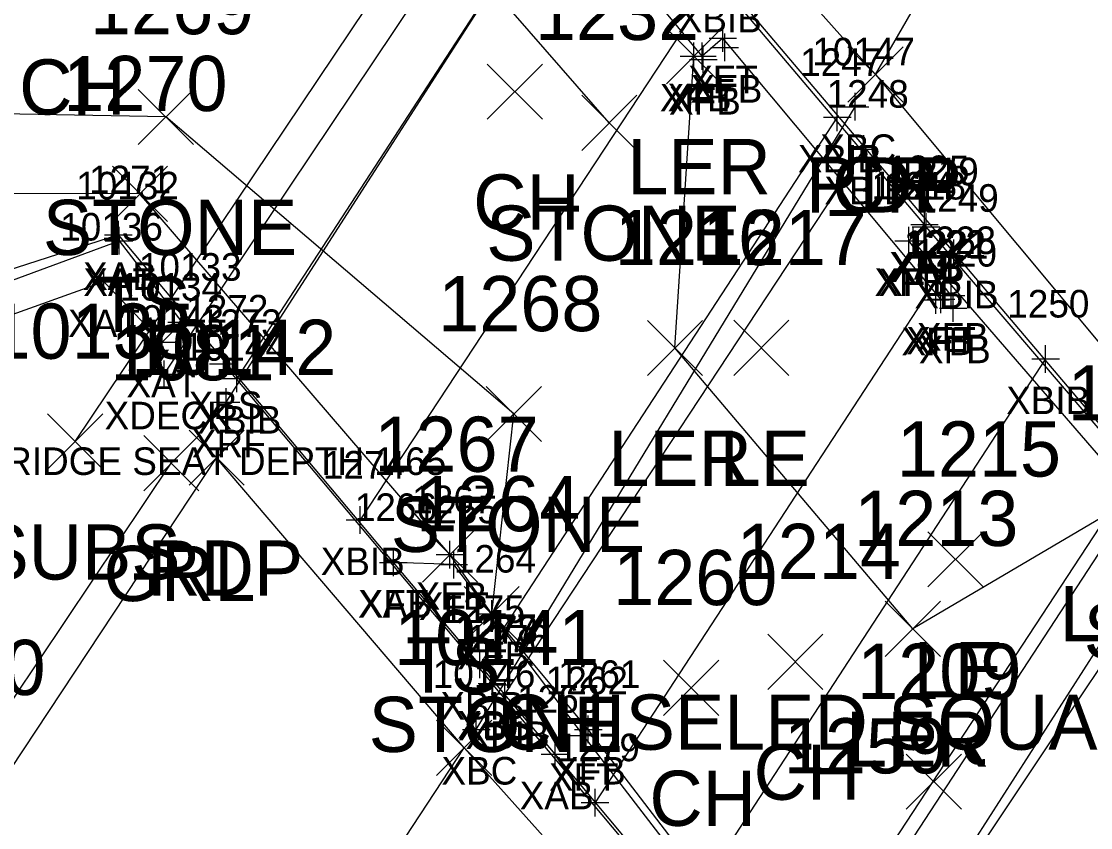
# Model space of a CAD drawing. Extents: x 1651685 to 1653558, y 889533 to 891085.
# Drawn here: x 1652681.1 to 1652719.83, y 890246.97 to 890276.18 of the extents above; entities that cross this region are included whole.
import ezdxf

# ---------------------------------------------------------------- set-up
doc = ezdxf.new("R2010")
doc.units = 0
for name, color, linetype in [('B_A', 7, 'Continuous'), ('B_C', 7, 'Continuous'), ('B_I', 7, 'Continuous'), ('B_TIC', 7, 'Continuous'), ('BB', 7, 'Continuous'), ('BELB', 7, 'Continuous'), ('BFT', 7, 'Continuous'), ('BR', 7, 'Continuous'), ('BSE', 7, 'Continuous'), ('BSUBM', 7, 'Continuous'), ('C_C', 7, 'Continuous'), ('L_A', 7, 'Continuous'), ('L_I', 7, 'Continuous'), ('L_TIC', 7, 'Continuous'), ('LARO', 7, 'Continuous'), ('LASF', 7, 'Continuous'), ('LELB', 7, 'Continuous'), ('P_A', 7, 'Continuous'), ('P_I', 7, 'Continuous'), ('P_TIC', 7, 'Continuous'), ('PET', 7, 'Continuous'), ('PRC', 7, 'Continuous'), ('R_A', 7, 'Continuous'), ('R_I', 7, 'Continuous'), ('R_TIC', 7, 'Continuous'), ('RGR', 7, 'Continuous'), ('U_A', 7, 'Continuous'), ('U_I', 7, 'Continuous'), ('U_TIC', 7, 'Continuous'), ('USA', 7, 'Continuous')]:
    doc.layers.add(name, color=color, linetype=linetype)

msp = doc.modelspace()

# ---------------------------------------------------------------- linework, layer by layer
at = {"layer": 'B_TIC'}
for p, q in [((1652706.515, 890275.575), (1652706.59, 890275.575)), ((1652706.585, 890275.238), (1652706.66, 890275.238)), ((1652705.47, 890274.919), (1652705.545, 890274.919)), ((1652705.769, 890274.921), (1652705.844, 890274.921)), ((1652705.806, 890274.805), (1652705.881, 890274.805)), ((1652711.308, 890273.088), (1652711.383, 890273.088)), ((1652710.662, 890272.707), (1652710.737, 890272.707)), ((1652711.622, 890271.554), (1652711.697, 890271.554)), ((1652713.821, 890268.822), (1652713.896, 890268.822)), ((1652713.821, 890268.822), (1652713.896, 890268.822)), ((1652713.877, 890268.743), (1652713.953, 890268.743)), ((1652713.877, 890268.743), (1652713.953, 890268.743)), ((1652684.618, 890268.453), (1652684.694, 890268.453)), ((1652684.644, 890268.232), (1652684.719, 890268.232)), ((1652713.249, 890268.232), (1652713.324, 890268.232)), ((1652713.408, 890268.228), (1652713.483, 890268.228)), ((1652714.885, 890267.783), (1652714.96, 890267.783)), ((1652684.09, 890266.74), (1652684.166, 890266.74)), ((1652714.785, 890266.251), (1652714.861, 890266.251)), ((1652714.228, 890266.087), (1652714.303, 890266.087)), ((1652714.414, 890266.114), (1652714.49, 890266.114)), ((1652714.859, 890265.796), (1652714.934, 890265.796)), ((1652686.913, 890265.285), (1652686.988, 890265.285)), ((1652686.206, 890264.564), (1652686.282, 890264.564)), ((1652718.208, 890263.952), (1652718.283, 890263.952)), ((1652688.422, 890263.77), (1652688.498, 890263.77)), ((1652686.275, 890263.4), (1652686.351, 890263.4)), ((1652688.906, 890263.246), (1652688.982, 890263.246)), ((1652688.522, 890262.387), (1652688.598, 890262.387)), ((1652693.375, 890258.116), (1652693.451, 890258.116)), ((1652696.63, 890256.861), (1652696.706, 890256.861)), ((1652694.58, 890256.579), (1652694.655, 890256.579)), ((1652694.58, 890256.579), (1652694.655, 890256.579)), ((1652696.767, 890256.497), (1652696.842, 890256.497)), ((1652698.141, 890254.709), (1652698.217, 890254.709)), ((1652697.712, 890252.882), (1652697.788, 890252.882)), ((1652698.154, 890252.192), (1652698.23, 890252.192)), ((1652698.188, 890252.136), (1652698.264, 890252.136)), ((1652698.619, 890251.814), (1652698.695, 890251.814)), ((1652697.585, 890250.528), (1652697.66, 890250.528)), ((1652701.471, 890250.302), (1652701.546, 890250.302)), ((1652701.64, 890250.529), (1652701.715, 890250.529)), ((1652700.436, 890249.63), (1652700.511, 890249.63)), ((1652701.886, 890247.873), (1652701.962, 890247.873))]:
    msp.add_line(p, q, dxfattribs=at)
for points in [[(1652706.512, 890275.075), (1652706.512, 890276.075)], [(1652706.012, 890275.575), (1652707.012, 890275.575)], [(1652706.581, 890274.738), (1652706.581, 890275.738)], [(1652705.466, 890274.419), (1652705.466, 890275.419)], [(1652705.765, 890274.421), (1652705.765, 890275.421)], [(1652705.803, 890274.305), (1652705.803, 890275.305)], [(1652706.081, 890275.238), (1652707.081, 890275.238)], [(1652704.966, 890274.919), (1652705.966, 890274.919)], [(1652705.265, 890274.921), (1652706.265, 890274.921)], [(1652705.303, 890274.805), (1652706.303, 890274.805)], [(1652711.304, 890272.588), (1652711.304, 890273.588)], [(1652710.658, 890272.207), (1652710.658, 890273.207)], [(1652710.804, 890273.088), (1652711.804, 890273.088)], [(1652710.158, 890272.707), (1652711.158, 890272.707)], [(1652711.618, 890271.054), (1652711.618, 890272.054)], [(1652711.118, 890271.554), (1652712.118, 890271.554)], [(1652713.817, 890268.322), (1652713.817, 890269.322)], [(1652713.817, 890268.322), (1652713.817, 890269.322)], [(1652713.874, 890268.243), (1652713.874, 890269.243)], [(1652713.874, 890268.243), (1652713.874, 890269.243)], [(1652684.615, 890267.953), (1652684.615, 890268.953)], [(1652684.64, 890267.732), (1652684.64, 890268.732)], [(1652713.245, 890267.732), (1652713.245, 890268.732)], [(1652713.317, 890268.822), (1652714.317, 890268.822)], [(1652713.317, 890268.822), (1652714.317, 890268.822)], [(1652713.374, 890268.743), (1652714.374, 890268.743)], [(1652713.374, 890268.743), (1652714.374, 890268.743)], [(1652713.404, 890267.728), (1652713.404, 890268.728)], [(1652684.115, 890268.453), (1652685.115, 890268.453)], [(1652684.14, 890268.232), (1652685.14, 890268.232)], [(1652712.745, 890268.232), (1652713.745, 890268.232)], [(1652712.904, 890268.228), (1652713.904, 890268.228)], [(1652714.881, 890267.283), (1652714.881, 890268.283)], [(1652714.381, 890267.783), (1652715.381, 890267.783)], [(1652684.087, 890266.24), (1652684.087, 890267.24)], [(1652683.587, 890266.74), (1652684.587, 890266.74)], [(1652714.224, 890265.587), (1652714.224, 890266.587)], [(1652714.411, 890265.614), (1652714.411, 890266.614)], [(1652714.782, 890265.751), (1652714.782, 890266.751)], [(1652714.282, 890266.251), (1652715.282, 890266.251)], [(1652714.855, 890265.296), (1652714.855, 890266.296)], [(1652686.909, 890264.785), (1652686.909, 890265.785)], [(1652713.724, 890266.087), (1652714.724, 890266.087)], [(1652713.911, 890266.114), (1652714.911, 890266.114)], [(1652714.355, 890265.796), (1652715.355, 890265.796)], [(1652686.203, 890264.064), (1652686.203, 890265.064)], [(1652686.409, 890265.285), (1652687.409, 890265.285)], [(1652685.703, 890264.564), (1652686.703, 890264.564)], [(1652688.419, 890263.27), (1652688.419, 890264.27)], [(1652718.204, 890263.452), (1652718.204, 890264.452)], [(1652686.272, 890262.9), (1652686.272, 890263.9)], [(1652717.704, 890263.952), (1652718.704, 890263.952)], [(1652687.919, 890263.77), (1652688.919, 890263.77)], [(1652688.903, 890262.746), (1652688.903, 890263.746)], [(1652685.772, 890263.4), (1652686.772, 890263.4)], [(1652688.403, 890263.246), (1652689.403, 890263.246)], [(1652688.519, 890261.887), (1652688.519, 890262.887)], [(1652688.019, 890262.387), (1652689.019, 890262.387)], [(1652693.372, 890257.616), (1652693.372, 890258.616)], [(1652692.872, 890258.116), (1652693.872, 890258.116)], [(1652696.627, 890256.361), (1652696.627, 890257.361)], [(1652694.576, 890256.079), (1652694.576, 890257.079)], [(1652694.576, 890256.079), (1652694.576, 890257.079)], [(1652696.127, 890256.861), (1652697.127, 890256.861)], [(1652696.763, 890255.997), (1652696.763, 890256.997)], [(1652694.076, 890256.579), (1652695.076, 890256.579)], [(1652694.076, 890256.579), (1652695.076, 890256.579)], [(1652696.263, 890256.497), (1652697.263, 890256.497)], [(1652698.138, 890254.209), (1652698.138, 890255.209)], [(1652697.638, 890254.709), (1652698.638, 890254.709)], [(1652697.709, 890252.382), (1652697.709, 890253.382)], [(1652697.209, 890252.882), (1652698.209, 890252.882)], [(1652698.151, 890251.692), (1652698.151, 890252.692)], [(1652698.185, 890251.636), (1652698.185, 890252.636)], [(1652698.616, 890251.314), (1652698.616, 890252.314)], [(1652697.651, 890252.192), (1652698.651, 890252.192)], [(1652697.685, 890252.136), (1652698.685, 890252.136)], [(1652698.116, 890251.814), (1652699.116, 890251.814)], [(1652697.581, 890250.028), (1652697.581, 890251.028)], [(1652701.467, 890249.802), (1652701.467, 890250.802)], [(1652701.636, 890250.029), (1652701.636, 890251.029)], [(1652697.081, 890250.528), (1652698.081, 890250.528)], [(1652700.967, 890250.302), (1652701.967, 890250.302)], [(1652701.136, 890250.529), (1652702.136, 890250.529)], [(1652700.432, 890249.13), (1652700.432, 890250.13)], [(1652699.932, 890249.63), (1652700.932, 890249.63)], [(1652701.883, 890247.373), (1652701.883, 890248.373)], [(1652701.383, 890247.873), (1652702.383, 890247.873)]]:
    msp.add_lwpolyline(points, dxfattribs=at)
at = {"layer": 'BB'}
for points in [[(1652701.657, 890282.829), (1652688.903, 890263.246)], [(1652706.306, 890277.782), (1652693.372, 890258.116)], [(1652710.658, 890272.707), (1652697.709, 890252.882)], [(1652711.618, 890271.554), (1652698.616, 890251.814)], [(1652714.881, 890267.783), (1652701.883, 890247.873)], [(1652718.204, 890263.952), (1652705.167, 890243.967)], [(1652721.557, 890259.987), (1652708.489, 890240.052)]]:
    msp.add_lwpolyline(points, dxfattribs=at)
at = {"layer": 'BELB'}
for points in [[(1652686.272, 890263.4), (1652701.462, 890286.084)], [(1652697.581, 890250.528), (1652711.304, 890273.088)], [(1652709.172, 890236.253), (1652723.445, 890257.661), (1652723.976, 890257.346), (1652725.092, 890258.712), (1652723.412, 890260.555)]]:
    msp.add_lwpolyline(points, dxfattribs=at)
at = {"layer": 'BFT'}
for points in [[(1652714.411, 890266.114), (1652706.512, 890275.575), (1652705.765, 890274.921), (1652698.946, 890283.164), (1652700.062, 890284.332), (1652698.253, 890286.301)], [(1652714.782, 890266.251), (1652713.245, 890268.232), (1652713.817, 890268.822)], [(1652730.043, 890250.298), (1652728.979, 890249.404), (1652721.281, 890259.118), (1652713.404, 890268.228), (1652713.874, 890268.743)], [(1652708.912, 890224.583), (1652712.61, 890236.191), (1652701.636, 890250.529), (1652698.138, 890254.709), (1652696.627, 890256.861)], [(1652708.658, 890224.484), (1652712.411, 890236.055), (1652701.467, 890250.302), (1652696.763, 890256.497), (1652694.576, 890256.579)]]:
    msp.add_lwpolyline(points, dxfattribs=at)
at = {"layer": 'BR'}
for points in [[(1652688.519, 890262.387), (1652701.676, 890282.871), (1652702.022, 890283.431)], [(1652708.535, 890239.146), (1652722.284, 890260.183)]]:
    msp.add_lwpolyline(points, dxfattribs=at)
at = {"layer": 'BSE'}
for points in [[(1652702.322, 890282.616), (1652723.867, 890257.21)], [(1652688.419, 890263.77), (1652698.151, 890252.192), (1652698.185, 890252.136), (1652710.4, 890237.557)]]:
    msp.add_lwpolyline(points, dxfattribs=at)
at = {"layer": 'BSUBM'}
for points in [[(1652730.91, 890251.239), (1652729.609, 890250.415), (1652721.751, 890259.535), (1652713.874, 890268.743), (1652713.817, 890268.822), (1652702.155, 890282.607), (1652701.912, 890282.515), (1652698.364, 890286.414), (1652698.385, 890299.877), (1652698.504, 890301.956), (1652700.485, 890302.125)], [(1652674.277, 890264.417), (1652684.64, 890268.232), (1652686.909, 890265.285), (1652686.203, 890264.564), (1652684.087, 890266.74), (1652675.355, 890263.62)], [(1652707.273, 890221.555), (1652712.176, 890235.573), (1652700.432, 890249.63), (1652694.576, 890256.579), (1652684.615, 890268.453), (1652678.722, 890266.546)]]:
    msp.add_lwpolyline(points, dxfattribs=at)
at = {"layer": 'L_TIC'}
for points in [[(1652704.466, 890273.919), (1652706.466, 890275.919)], [(1652706.466, 890273.919), (1652704.466, 890275.919)], [(1652697.98, 890272.636), (1652699.98, 890274.636)], [(1652699.98, 890272.636), (1652697.98, 890274.636)], [(1652685.335, 890271.718), (1652687.335, 890273.718)], [(1652687.335, 890271.718), (1652685.335, 890273.718)], [(1652701.399, 890271.508), (1652703.399, 890273.508)], [(1652703.399, 890271.508), (1652701.399, 890273.508)], [(1652684.397, 890268.933), (1652686.397, 890270.933)], [(1652686.397, 890268.933), (1652684.397, 890270.933)], [(1652703.778, 890263.349), (1652705.778, 890265.349)], [(1652705.778, 890263.349), (1652703.778, 890265.349)], [(1652706.905, 890263.352), (1652708.905, 890265.352)], [(1652708.905, 890263.352), (1652706.905, 890265.352)], [(1652697.939, 890260.957), (1652699.939, 890262.957)], [(1652699.939, 890260.957), (1652697.939, 890262.957)], [(1652695.627, 890255.861), (1652697.627, 890257.861)], [(1652697.627, 890255.861), (1652695.627, 890257.861)], [(1652713.938, 890255.689), (1652715.938, 890257.689)], [(1652715.938, 890255.689), (1652713.938, 890257.689)], [(1652697.138, 890253.709), (1652699.138, 890255.709)], [(1652699.138, 890253.709), (1652697.138, 890255.709)], [(1652712.393, 890253.174), (1652714.393, 890255.174)], [(1652714.393, 890253.174), (1652712.393, 890255.174)], [(1652708.139, 890251.977), (1652710.139, 890253.977)], [(1652710.139, 890251.977), (1652708.139, 890253.977)], [(1652704.363, 890251.031), (1652706.363, 890253.031)], [(1652706.363, 890251.031), (1652704.363, 890253.031)], [(1652713.156, 890247.634), (1652715.156, 890249.634)], [(1652715.156, 890247.634), (1652713.156, 890249.634)]]:
    msp.add_lwpolyline(points, dxfattribs=at)
at = {"layer": 'LARO'}
msp.add_lwpolyline([(1652721.127, 890258.721), (1652713.393, 890254.174), (1652704.778, 890264.349), (1652705.466, 890274.919)], dxfattribs=at)
at = {"layer": 'LASF'}
for points in [[(1652702.399, 890272.508), (1652693.116, 890283.145), (1652692.048, 890298.23), (1652676.075, 890310.97), (1652670.462, 890321.805), (1652673.396, 890326.853)], [(1652698.138, 890254.709), (1652698.939, 890261.957), (1652686.335, 890272.718), (1652676.405, 890272.911), (1652664.656, 890280.5), (1652655.636, 890289.648)]]:
    msp.add_lwpolyline(points, dxfattribs=at)
at = {"layer": 'LELB'}
msp.add_lwpolyline([(1652696.627, 890256.861), (1652685.397, 890269.933), (1652673.03, 890269.951)], dxfattribs=at)
at = {"layer": 'P_TIC'}
for points in [[(1652711.038, 890273.257), (1652713.038, 890275.257)], [(1652713.038, 890273.257), (1652711.038, 890275.257)], [(1652711.038, 890273.257), (1652713.038, 890275.257)], [(1652713.038, 890273.257), (1652711.038, 890275.257)], [(1652687.173, 890259.372), (1652689.173, 890261.372)], [(1652689.173, 890259.372), (1652687.173, 890261.372)], [(1652687.173, 890259.372), (1652689.173, 890261.372)], [(1652689.173, 890259.372), (1652687.173, 890261.372)], [(1652696.139, 890248.857), (1652698.139, 890250.857)], [(1652698.139, 890248.857), (1652696.139, 890250.857)], [(1652696.139, 890248.857), (1652698.139, 890250.857)], [(1652698.139, 890248.857), (1652696.139, 890250.857)]]:
    msp.add_lwpolyline(points, dxfattribs=at)
at = {"layer": 'PET'}
for points in [[(1652703.162, 890284.218), (1652712.038, 890274.257), (1652722.331, 890261.916), (1652735.137, 890284.012), (1652751.621, 890318.115), (1652767.723, 890357.351), (1652783.179, 890400.145), (1652797.7, 890444.761), (1652815.977, 890499.358)], [(1652310.071, 889873.858), (1652345.018, 889890.876), (1652381.133, 889910.269), (1652416.225, 889931.732), (1652447.247, 889952.285), (1652474.07, 889972.993), (1652503.702, 889997.944), (1652534.457, 890027.787), (1652563.385, 890057.924), (1652590.108, 890087.923), (1652620.326, 890123.876), (1652646.593, 890156.843), (1652667.225, 890184.01), (1652673.844, 890192.76), (1652698.186, 890224.989), (1652707.052, 890238.801), (1652697.139, 890249.857), (1652688.173, 890260.372)], [(1652333.651, 889912.667), (1652369.12, 889931.534), (1652403.155, 889952.408), (1652433.06, 889972.257), (1652459.319, 889992.677), (1652488.38, 890016.936), (1652517.957, 890045.24), (1652545.959, 890074.028), (1652572.077, 890103.378), (1652602.102, 890139.625), (1652627.16, 890172.833), (1652646.677, 890199.415), (1652655.748, 890211.753), (1652675.089, 890240.598), (1652688.173, 890260.372)]]:
    msp.add_lwpolyline(points, dxfattribs=at)
at = {"layer": 'PRC'}
for points in [[(1652712.038, 890274.257), (1652722.864, 890292.979), (1652739.686, 890324.96), (1652756.287, 890362.602), (1652772.674, 890406.812), (1652786.214, 890448.938), (1652804.537, 890503.78)], [(1652339.131, 889902.361), (1652374.757, 889921.453), (1652409.696, 889942.759), (1652439.668, 889962.958), (1652466.375, 889983.158), (1652495.638, 890007.899), (1652525.652, 890036.364), (1652554.01, 890065.879), (1652580.922, 890096.263), (1652611.449, 890132.238), (1652636.96, 890165.085), (1652656.957, 890191.595), (1652665.106, 890202.523), (1652686.512, 890233.671), (1652697.139, 890249.857)]]:
    msp.add_lwpolyline(points, dxfattribs=at)
at = {"layer": 'R_TIC'}
for points in [[(1652685.531, 890259.177), (1652687.531, 890261.177)], [(1652687.531, 890259.177), (1652685.531, 890261.177)]]:
    msp.add_lwpolyline(points, dxfattribs=at)
at = {"layer": 'RGR'}
msp.add_lwpolyline([(1652678.884, 890248.772), (1652686.531, 890260.177)], dxfattribs=at)
at = {"layer": 'U_TIC'}
for points in [[(1652682.047, 890259.957), (1652684.047, 890261.957)], [(1652684.047, 890259.957), (1652682.047, 890261.957)]]:
    msp.add_lwpolyline(points, dxfattribs=at)
at = {"layer": 'USA'}
for points in [[(1652683.047, 890260.957), (1652702.995, 890290.696)], [(1652723.048, 890258.093), (1652710.168, 890238)]]:
    msp.add_lwpolyline(points, dxfattribs=at)

# ---------------------------------------------------------------- texts
at = {"layer": 'B_A'}
for s, p in [('XBIB', (1652704.877, 890275.782)), ('XFT', (1652705.256, 890273.575)), ('XFB', (1652704.226, 890272.919)), ('XFT', (1652704.509, 890272.921)), ('XFB', (1652705.341, 890273.238)), ('XFB', (1652704.562, 890272.805)), ('XBC', (1652710.041, 890271.088)), ('XBIB', (1652709.229, 890270.707)), ('XBIB', (1652710.189, 890269.554)), ('XAB', (1652712.538, 890266.822)), ('XFB', (1652712.577, 890266.822)), ('XAB', (1652712.594, 890266.743)), ('XFT', (1652712.618, 890266.743)), ('XAB', (1652683.335, 890266.453)), ('XAT', (1652683.345, 890266.232)), ('XFB', (1652712.005, 890266.232)), ('XFT', (1652712.148, 890266.228)), ('XBIB', (1652713.452, 890265.783)), ('XAT', (1652682.792, 890264.74)), ('XFB', (1652712.984, 890264.087)), ('XFT', (1652713.155, 890264.114)), ('XFB', (1652713.542, 890264.251)), ('XFB', (1652713.615, 890263.796)), ('XAT', (1652685.614, 890263.285)), ('XAT', (1652684.908, 890262.564)), ('XBS', (1652687.159, 890261.77)), ('XBIB', (1652716.775, 890261.952)), ('XDECK', (1652684.114, 890261.4)), ('XBIB', (1652687.474, 890261.246)), ('XRF', (1652687.279, 890260.387)), ('XBIB', (1652691.942, 890256.116)), ('XFB', (1652695.386, 890254.861)), ('XAB', (1652693.297, 890254.579)), ('XFT', (1652693.321, 890254.579)), ('XFT', (1652695.507, 890254.497)), ('XFB', (1652696.898, 890252.709)), ('XBIB', (1652696.28, 890250.882)), ('XBS', (1652696.891, 890250.192)), ('XBS', (1652696.925, 890250.136)), ('XBIB', (1652697.187, 890249.814)), ('XBC', (1652696.317, 890248.528)), ('XFB', (1652700.396, 890248.529)), ('XFT', (1652700.211, 890248.302)), ('XAB', (1652699.153, 890247.63))]:
    msp.add_text(s, height=1, dxfattribs=at).set_placement(p)
at = {"layer": 'B_C'}
msp.add_text('BRIDGE SEAT DEPTH 1.65', height=1, dxfattribs=at).set_placement((1652679.62, 890259.746))
at = {"layer": 'B_I'}
for s, p in [('10147', (1652709.753, 890274.588)), ('1247', (1652709.312, 890274.207)), ('1248', (1652710.272, 890273.054)), ('1225', (1652712.471, 890270.322)), ('1225', (1652712.471, 890270.322)), ('1219', (1652712.807, 890270.243)), ('1219', (1652712.807, 890270.243)), ('1271', (1652683.552, 890269.953)), ('10132', (1652683.089, 890269.732)), ('1224', (1652711.899, 890269.732)), ('1218', (1652712.341, 890269.728)), ('1249', (1652713.531, 890269.283)), ('10136', (1652682.508, 890268.24)), ('1222', (1652713.065, 890267.614)), ('1221', (1652713.162, 890267.587)), ('1223', (1652713.436, 890267.751)), ('1220', (1652713.466, 890267.296)), ('10133', (1652685.358, 890266.785)), ('10134', (1652684.652, 890266.064)), ('1272', (1652687.072, 890265.27)), ('1250', (1652716.815, 890265.452)), ('10143', (1652684.721, 890264.9)), ('1273', (1652687.556, 890264.746)), ('10144', (1652686.968, 890263.887)), ('1274', (1652692.025, 890259.616)), ('1267', (1652695.257, 890258.361)), ('1266', (1652693.179, 890258.079)), ('1266', (1652693.179, 890258.079)), ('1265', (1652695.393, 890257.997)), ('1264', (1652696.768, 890256.209)), ('1275', (1652696.363, 890254.382)), ('1277', (1652696.804, 890253.692)), ('1278', (1652696.839, 890253.636)), ('1276', (1652697.242, 890253.314)), ('10146', (1652696.003, 890252.028)), ('1261', (1652700.55, 890252.029)), ('1262', (1652700.097, 890251.802)), ('1263', (1652699.062, 890251.13)), ('1279', (1652700.533, 890249.373))]:
    msp.add_text(s, height=1, dxfattribs=at).set_placement(p)
at = {"layer": 'C_C'}
msp.add_text('CHISELED SQUARE ON BRIDGE ABUT', height=2, dxfattribs=at).set_placement((1652698.386, 890249.79))
at = {"layer": 'L_A'}
for s, p in [('CH', (1652681.019, 890272.807)), ('LER', (1652703.049, 890269.919)), ('CH', (1652697.468, 890268.636)), ('STONE', (1652681.878, 890267.718)), ('STONE', (1652697.942, 890267.508)), ('TS', (1652683.807, 890264.933)), ('LER', (1652702.361, 890259.349)), ('LE', (1652706.393, 890259.352)), ('STONE', (1652694.482, 890256.957)), ('LER', (1652718.71, 890253.721)), ('TS', (1652695.036, 890251.861)), ('LE', (1652713.426, 890251.689)), ('STONE', (1652693.681, 890249.709)), ('LER', (1652710.976, 890249.174)), ('CH', (1652707.627, 890247.977)), ('CH', (1652703.851, 890247.031))]:
    msp.add_text(s, height=2, dxfattribs=at).set_placement(p)
at = {"layer": 'L_I'}
for s, p in [('1269', (1652683.587, 890275.718)), ('1232', (1652699.706, 890275.508)), ('1270', (1652682.618, 890272.933)), ('1216', (1652702.598, 890267.349)), ('1217', (1652705.779, 890267.352)), ('1268', (1652696.199, 890264.957)), ('1212', (1652719.001, 890261.721)), ('1267', (1652693.887, 890259.861)), ('1215', (1652712.812, 890259.689)), ('1264', (1652695.398, 890257.709)), ('1213', (1652711.268, 890257.174)), ('1214', (1652707.013, 890255.977)), ('1260', (1652702.536, 890255.031)), ('1209', (1652711.377, 890251.634)), ('1259', (1652708.719, 890248.933))]:
    msp.add_text(s, height=2, dxfattribs=at).set_placement(p)
at = {"layer": 'P_A'}
for s, p in [('RDP', (1652709.526, 890269.257)), ('CR', (1652710.471, 890269.257)), ('RDP', (1652685.661, 890255.372)), ('RDP', (1652685.661, 890255.372))]:
    msp.add_text(s, height=2, dxfattribs=at).set_placement(p)
at = {"layer": 'P_I'}
for s, p in [('10142', (1652685.071, 890263.372)), ('10142', (1652685.071, 890263.372)), ('10141', (1652694.604, 890252.857)), ('10141', (1652694.604, 890252.857))]:
    msp.add_text(s, height=2, dxfattribs=at).set_placement(p)
at = {"layer": 'R_A'}
msp.add_text('GRL', height=2, dxfattribs=at).set_placement((1652684.075, 890255.177))
at = {"layer": 'R_I'}
for s, p in [('1081', (1652684.327, 890263.177)), ('1080', (1652676.026, 890251.772)), ('1080', (1652676.026, 890251.772))]:
    msp.add_text(s, height=2, dxfattribs=at).set_placement(p)
at = {"layer": 'U_A'}
for p in [(1652679.582, 890255.957), (1652719.583, 890253.093)]:
    msp.add_text('SUBS', height=2, dxfattribs=at).set_placement(p)
at = {"layer": 'U_I'}
msp.add_text('10135', height=2, dxfattribs=at).set_placement((1652679.945, 890263.957))

doc.saveas('drawing.dxf')
